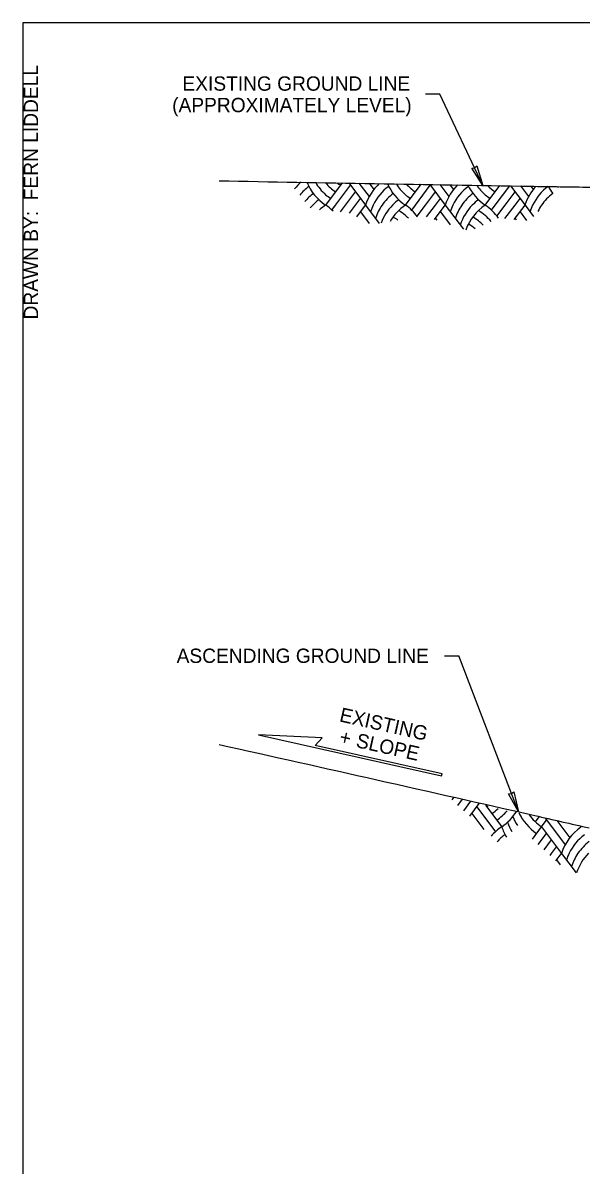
# Model space of a CAD drawing. Extents: x 99862 to 103151, y 100000 to 102076.
# Drawn here: x 99862 to 100486, y 100799 to 102076 of the extents above; entities that cross this region are included whole.
import ezdxf

# ---------------------------------------------------------------- set-up
doc = ezdxf.new("R2010")
doc.units = 0
for name, color, linetype in [('Level 1', 7, 'Continuous'), ('Level 15', 7, 'Continuous'), ('Level 16', 7, 'Continuous'), ('Level 20', 7, 'Continuous'), ('Level 3', 7, 'Continuous'), ('Level 4', 7, 'Continuous'), ('Level 62', 7, 'Continuous')]:
    doc.layers.add(name, color=color, linetype=linetype)

msp = doc.modelspace()

# ---------------------------------------------------------------- linework, layer by layer
at = {"layer": 'Level 1'}
msp.add_lwpolyline([(99862, 99999.5), (103151, 99999.5), (103151, 102075.5), (99862, 102075.5)], close=True, dxfattribs=at)
at = {"layer": 'Level 15'}
for p, q in [((100327.9, 101995.7), (100311.9, 101995.7)), ((100376, 101893.9), (100327.9, 101995.7)), ((100333.2, 101368.5), (100349.2, 101368.5)), ((100415.6, 101194.2), (100349.2, 101368.5))]:
    msp.add_line(p, q, dxfattribs=at)
for points in [[(100376, 101893.9), (100363.6, 101913.3), (100366.7, 101913.6), (100369, 101915.8)], [(100415.6, 101194.2), (100404.7, 101214.4), (100407.8, 101214.5), (100410.3, 101216.6)]]:
    msp.add_lwpolyline(points, close=True, dxfattribs=at)
at = {"layer": 'Level 16'}
for points in [[(100081.3, 101899.1), (100428.6, 101893), (100496, 101892)], [(100081.3, 101269.4), (100433.8, 101190.1), (100494.6, 101176.2)]]:
    msp.add_spline(points, degree=3, dxfattribs=at)
at = {"layer": 'Level 3'}
msp.add_lwpolyline([(100330.3, 101236.6), (100188.5, 101268.4), (100196.2, 101276.8), (100125.2, 101280.1), (100329.7, 101234.2)], close=True, dxfattribs=at)
at = {"layer": 'Level 4'}
for p, q in [((100169.8, 101897.7), (100171, 101896)), ((100200.3, 101871.9), (100219, 101896.8)), ((100211.4, 101871.9), (100228.1, 101894.1)), ((100226.2, 101896.7), (100244.8, 101871.9)), ((100237.5, 101896.5), (100248.9, 101881.4)), ((100248.8, 101896.3), (100254, 101889.3)), ((100260.1, 101896.1), (100260.1, 101896)), ((100289.4, 101871.9), (100306.9, 101895.3)), ((100300.5, 101871.9), (100317.2, 101894.1)), ((100316.5, 101895.1), (100333.9, 101871.9)), ((100327.8, 101894.9), (100337.9, 101881.4)), ((100339.1, 101894.7), (100343.1, 101889.3)), ((100378.5, 101871.9), (100394.9, 101893.7)), ((100389.6, 101871.9), (100405.9, 101893.5)), ((100406.8, 101893.5), (100423, 101871.9)), ((100418.1, 101893.3), (100427, 101881.4)), ((100429.3, 101893.2), (100432.2, 101889.3)), ((100222.6, 101871.9), (100233.7, 101886.7)), ((100233.7, 101871.9), (100239.3, 101879.3)), ((100311.7, 101871.9), (100322.8, 101886.7)), ((100322.8, 101871.9), (100328.4, 101879.3)), ((100400.8, 101871.9), (100411.9, 101886.7)), ((100411.9, 101871.9), (100417.5, 101879.3)), ((100207.3, 101866.3), (100211.4, 101871.9)), ((100217, 101864.5), (100222.6, 101871.9)), ((100227, 101863), (100233.7, 101871.9)), ((100235, 101858.8), (100244.8, 101871.9)), ((100244.8, 101871.9), (100260.1, 101851.5)), ((100296.4, 101866.3), (100300.5, 101871.9)), ((100302.5, 101859.6), (100311.7, 101871.9)), ((100312.9, 101858.7), (100322.8, 101871.9)), ((100321.8, 101855.7), (100333.9, 101871.9)), ((100333.9, 101871.9), (100354.1, 101845)), ((100385.5, 101866.3), (100389.6, 101871.9)), ((100391.6, 101859.6), (100400.8, 101871.9)), ((100400.6, 101856.8), (100411.9, 101871.9)), ((100410.9, 101855.7), (100423, 101871.9)), ((100423, 101871.9), (100432.5, 101859.2)), ((100239.3, 101864.4), (100249, 101851.4)), ((100322.8, 101857), (100324.4, 101854.9)), ((100328.4, 101864.4), (100339.3, 101849.9)), ((100411.9, 101857), (100413.1, 101855.4)), ((100417.5, 101864.4), (100424.8, 101854.7)), ((100341.5, 101207.5), (100343.9, 101210.7)), ((100348, 101201.4), (100353.2, 101208.3)), ((100354.6, 101195.3), (100362.5, 101205.9)), ((100361.2, 101189.2), (100371.8, 101203.4)), ((100378.9, 101201.6), (100396.9, 101177.5)), ((100363.5, 101192.4), (100376.9, 101174.5)), ((100369.1, 101199.8), (100390, 101172)), ((100434.5, 101183.1), (100438.6, 101188.5)), ((100431.2, 101163.8), (100441.5, 101177.5)), ((100441.5, 101177.5), (100447.9, 101186.1)), ((100441.5, 101177.5), (100463.8, 101147.8)), ((100445.7, 101186.7), (100467.8, 101157.3)), ((100458.6, 101184.4), (100472.9, 101165.3)), ((100437.8, 101157.7), (100447.1, 101170.1)), ((100444.4, 101151.6), (100452.6, 101162.7)), ((100452.6, 101147.8), (100458.2, 101155.2)), ((100450.9, 101145.5), (100452.6, 101147.8)), ((100457.5, 101139.4), (100463.8, 101147.8)), ((100458.2, 101140.4), (100462.3, 101135)), ((100463.8, 101147.8), (100480.1, 101126.1))]:
    msp.add_line(p, q, dxfattribs=at)
for centre, start, end in [((100209.5, 101854.8), 130.4502, 141.3333), ((100215, 101847.4), 126.3063, 140.8674), ((100231.7, 101918.7), 201.975, 236.0964), ((100237.3, 101926.1), 210.5915, 228.9599), ((100242.9, 101933.5), 220.1027, 220.9416), ((100242.9, 101933.5), 220.9415, 236.0964), ((100248.4, 101940.9), 231.2792, 236.0964), ((100298.6, 101854.8), 132.8727, 162.3566), ((100304.1, 101847.4), 126.3063, 154.2266), ((100320.8, 101918.7), 203.7728, 236.0964), ((100326.4, 101926.1), 212.5426, 228.9599), ((100332, 101933.5), 222.3219, 236.0964), ((100337.5, 101940.9), 234.0502, 236.0964), ((100387.7, 101854.8), 135.1616, 162.3566), ((100393.2, 101847.4), 126.3063, 154.2266), ((100409.9, 101918.7), 205.5608, 236.0964), ((100415.5, 101926.1), 214.4891, 228.9599), ((100421.1, 101933.5), 224.5538, 236.0964), ((100476.7, 101854.8), 137.2363, 162.3566), ((100482.3, 101847.4), 126.3063, 154.2266), ((100499, 101918.7), 207.2418, 217.0787), ((100504.6, 101926.1), 216.308, 217.6459), ((100220.6, 101839.9), 127.1006, 140.4023), ((100226.2, 101832.5), 126.331, 135.7128), ((100237.3, 101926.1), 228.9599, 236.0964), ((100309.7, 101839.9), 127.1006, 145.4911), ((100315.3, 101832.5), 126.331, 135.7128), ((100326.4, 101926.1), 228.9599, 236.0964), ((100398.8, 101839.9), 127.1006, 145.4911), ((100404.4, 101832.5), 126.331, 135.7128), ((100415.5, 101926.1), 228.9599, 236.0964), ((100487.9, 101839.9), 127.1006, 145.4911), ((100226.2, 101832.5), 135.7127, 139.9378), ((100231.7, 101825.1), 123.9036, 132.7397), ((100168.9, 101825.1), 45.372, 56.0963), ((100304.1, 101847.4), 154.2265, 162.3566), ((100309.7, 101839.9), 145.491, 162.3566), ((100315.3, 101832.5), 135.7127, 159.8967), ((100320.8, 101825.1), 123.9036, 149.6076), ((100252.4, 101817.7), 48.9597, 58.5465), ((100257.9, 101825.1), 36.936, 56.0963), ((100393.2, 101847.4), 154.2265, 162.3566), ((100398.8, 101839.9), 145.491, 162.3566), ((100404.4, 101832.5), 135.7127, 162.3566), ((100409.9, 101825.1), 123.9036, 160.3393), ((100341.5, 101817.7), 48.9597, 58.5465), ((100347, 101825.1), 34.8679, 56.0963), ((100482.3, 101847.4), 154.2265, 162.3566), ((100487.9, 101839.9), 145.491, 153.6376), ((100246.8, 101810.2), 52.7704, 59.3021), ((100252.4, 101817.7), 44.4717, 48.9597), ((100335.9, 101810.2), 44.1441, 59.3021), ((100341.5, 101817.7), 39.4563, 48.9597), ((100330.3, 101802.8), 48.9704, 58.4874), ((100348.8, 101246.6), 303.9036, 305.7971), ((100354.4, 101239.1), 303.9036, 313.0573), ((100359.9, 101231.7), 303.9036, 319.774), ((100365.5, 101224.3), 303.9036, 328.707), ((100461.8, 101209.4), 201.4344, 212.9256), ((100467.4, 101216.9), 204.8736, 236.0964), ((100467.4, 101216.9), 206.5545, 211.332), ((100472.9, 101224.3), 216.3984, 236.0964), ((100428.4, 101130.7), 123.9036, 140.1232), ((100450.7, 101194.6), 197.6434, 210.8534), ((100456.2, 101202), 200.2432, 211.892), ((100517.5, 101130.7), 124.9887, 162.3566), ((100434, 101123.3), 126.3063, 138.4553), ((100523, 101123.3), 126.7179, 154.2266), ((100528.6, 101115.9), 127.1006, 145.4911), ((100523, 101123.3), 154.2265, 162.3566), ((100528.6, 101115.9), 145.491, 162.3566), ((100534.2, 101108.5), 135.7127, 161.7965)]:
    msp.add_arc(centre, 56.4, start, end, dxfattribs=at)

# ---------------------------------------------------------------- texts
at = {"layer": 'Level 20'}
for s, p in [('EXISTING GROUND LINE', (100040.3, 101999.7)), ('(APPROXIMATELY LEVEL)', (100028.8, 101975.7)), ('ASCENDING GROUND LINE', (100033.8, 101360.5))]:
    msp.add_text(s, height=16, dxfattribs=at).set_placement(p)
for s, p in [('EXISTING', (100214.8, 101295.3)), ('+', (100214.6, 101270.7)), (' SLOPE', (100227.4, 101267.9))]:
    msp.add_text(s, height=16, rotation=347.3528, dxfattribs=at).set_placement(p)
at = {"layer": 'Level 62'}
msp.add_text('DRAWN BY:  FERN LIDDELL', height=16, rotation=90, dxfattribs=at).set_placement((99879, 101744.2))

doc.saveas('drawing.dxf')
